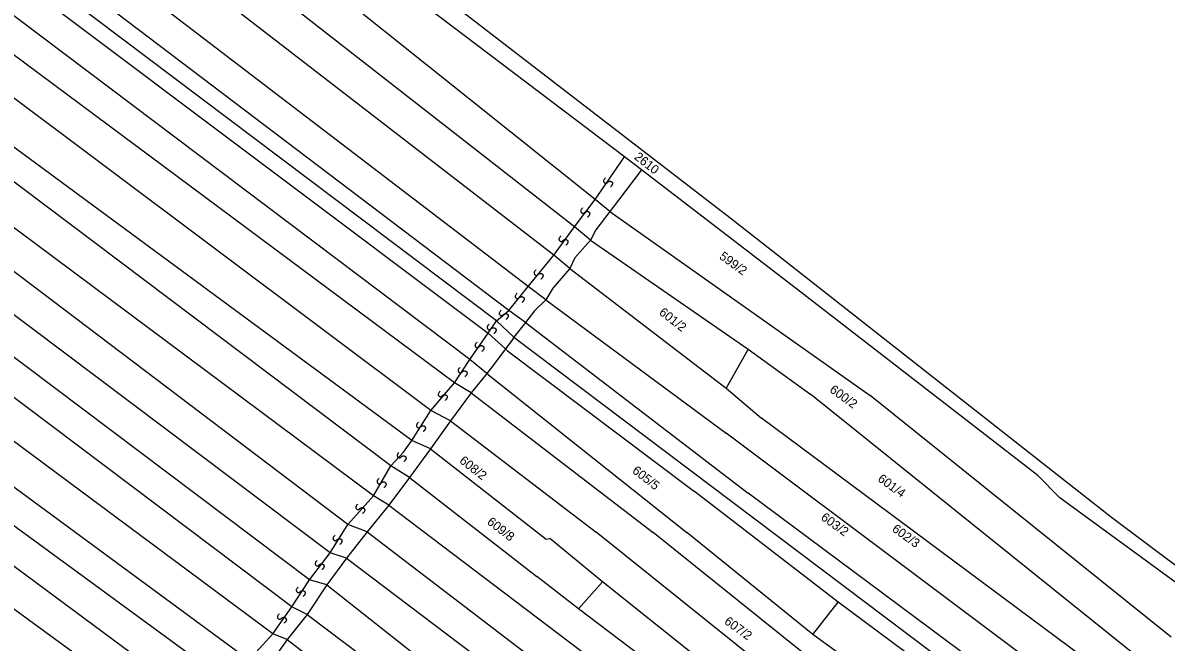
# Model space of a CAD drawing. Extents: x -581999 to -572728, y -1219553 to -1212032.
# Drawn here: x -577300.4 to -577046.4, y -1214683.3 to -1214545.7 of the extents above; entities that cross this region are included whole.
import ezdxf

# ---------------------------------------------------------------- set-up
doc = ezdxf.new("R2010")
doc.units = 0
for name, color, linetype in [('Vrstva 1', 7, 'Continuous'), ('Vrstva 2', 7, 'Continuous'), ('Vrstva 4', 7, 'Continuous'), ('Vrstva 6', 7, 'Continuous')]:
    doc.layers.add(name, color=color, linetype=linetype)

msp = doc.modelspace()

# ---------------------------------------------------------------- linework, layer by layer
at = {"layer": 'Vrstva 1'}
for p, q in [((-577173.2, -1214584.99), (-577388.875, -1214412.664)), ((-577177.814, -1214590.998), (-577393.467, -1214422.653)), ((-577182.425, -1214597.319), (-577397.014, -1214431.636)), ((-577188.1, -1214604.306), (-577399.497, -1214442.615)), ((-577192.44, -1214609.601), (-577401.268, -1214451.245)), ((-577195.178, -1214611.902), (-577402.391, -1214455.725)), ((-577403.465, -1214459.556), (-577196.983, -1214614.687)), ((-577201.069, -1214620.511), (-577405.865, -1214466.181)), ((-577204.509, -1214625.687), (-577407.639, -1214474.498)), ((-577209.72, -1214631.864), (-577409.72, -1214482.041)), ((-577213.976, -1214638.518), (-577414.023, -1214491.133)), ((-577218.587, -1214644.174), (-577416.861, -1214494.793)), ((-577222.489, -1214650.828), (-577423.245, -1214501.114)), ((-577228.164, -1214657.149), (-577427.856, -1214506.104)), ((-577232.066, -1214663.47), (-577433.26, -1214512.135)), ((-577236.677, -1214669.459), (-577438.393, -1214517.882)), ((-577240.578, -1214675.447), (-577443.108, -1214523.072)), ((-577244.835, -1214681.436), (-577449.136, -1214530.094)), ((-577250.174, -1214687.3), (-577454.627, -1214537.038)), ((-577253.702, -1214693.08), (-577459.151, -1214542.716)), ((-577258.313, -1214699.069), (-577462.971, -1214547.742)), ((-577262.569, -1214705.057), (-577467.937, -1214555.011)), ((-577162.904, -1214578.354), (-577166.7, -1214575.508)), ((-577170.008, -1214587.651), (-577173.2, -1214584.99)), ((-577174.264, -1214593.972), (-577177.814, -1214590.998)), ((-577178.875, -1214600.294), (-577182.425, -1214597.319)), ((-577184.195, -1214607.28), (-577188.1, -1214604.306)), ((-577188.711, -1214612.273), (-577192.44, -1214609.601)), ((-577191.284, -1214615.55), (-577195.178, -1214611.902)), ((-577193.144, -1214618.161), (-577196.983, -1214614.687)), ((-577191.713, -1214616.296), (-577193.144, -1214618.161)), ((-577191.284, -1214615.55), (-577065.274, -1214710.541)), ((-577193.144, -1214618.161), (-577195.94, -1214621.94)), ((-577192.695, -1214618.556), (-577193.144, -1214618.161)), ((-577197.32, -1214623.628), (-577201.069, -1214620.511)), ((-577200.79, -1214627.895), (-577204.509, -1214625.687)), ((-577205.332, -1214634.167), (-577209.72, -1214631.864)), ((-577209.808, -1214640.335), (-577213.976, -1214638.518)), ((-577214.507, -1214646.763), (-577218.587, -1214644.174)), ((-577219.047, -1214652.877), (-577222.489, -1214650.828)), ((-577223.897, -1214658.832), (-577228.164, -1214657.149)), ((-577228.435, -1214664.63), (-577232.066, -1214663.47)), ((-577232.819, -1214670.588), (-577236.677, -1214669.459)), ((-577237.207, -1214677.176), (-577240.578, -1214675.447)), ((-577241.673, -1214682.738), (-577244.835, -1214681.436))]:
    msp.add_line(p, q, dxfattribs=at)
for points in [[(-577166.7, -1214575.508), (-577251.364, -1214511.356), (-577280.716, -1214488.105)], [(-577143.306, -1214589.054), (-577228.604, -1214523.24), (-577244.701, -1214511.924)], [(-577039.499, -1214673.547), (-577070.025, -1214651.227), (-577074.89, -1214646.289), (-577128.538, -1214604.786), (-577162.904, -1214578.354), (-577168.07, -1214585.096)], [(-577168.07, -1214585.096), (-577170.008, -1214587.651), (-577173.08, -1214591.681)], [(-577170.008, -1214587.651), (-577112.132, -1214628.524)], [(-576930.254, -1214757.061), (-576935.99, -1214747.903), (-576959.905, -1214728.809), (-576982.36, -1214712.757), (-577058.553, -1214655.612), (-577135.842, -1214594.867), (-577143.306, -1214589.054)], [(-577173.08, -1214591.681), (-577174.264, -1214593.972), (-577177.778, -1214597.952)], [(-577174.264, -1214593.972), (-577139.259, -1214618.21)], [(-577177.778, -1214597.952), (-577178.875, -1214600.294), (-577182.634, -1214604.697)], [(-577178.875, -1214600.294), (-577144.115, -1214626.909)], [(-577182.634, -1214604.697), (-577184.195, -1214607.28), (-577186.702, -1214609.711)], [(-577186.702, -1214609.711), (-577188.711, -1214612.273), (-577191.284, -1214615.55), (-577191.713, -1214616.296)], [(-577184.195, -1214607.28), (-577144.115, -1214636.89)], [(-577188.711, -1214612.273), (-577139.236, -1214650.19)], [(-577192.695, -1214618.556), (-577151.196, -1214649.83)], [(-577139.259, -1214618.21), (-577144.115, -1214626.909)], [(-577139.259, -1214618.21), (-577125.314, -1214628.254)], [(-577195.94, -1214621.94), (-577197.32, -1214623.628), (-577200.79, -1214627.895)], [(-577197.32, -1214623.628), (-577152.883, -1214658.973)], [(-577144.115, -1214626.909), (-577136.312, -1214633.563)], [(-577200.79, -1214627.895), (-577205.332, -1214634.167)], [(-577200.79, -1214627.895), (-577160.362, -1214658.983)], [(-577049.661, -1214689.077), (-577125.314, -1214628.254)], [(-577045.273, -1214682.181), (-577112.132, -1214628.524)], [(-577205.332, -1214634.167), (-577209.808, -1214640.335)], [(-577205.332, -1214634.167), (-577173.006, -1214658.877)], [(-577053.701, -1214694.938), (-577136.312, -1214633.563)], [(-577058.086, -1214701.362), (-577144.115, -1214636.89)], [(-577209.808, -1214640.335), (-577214.507, -1214646.763)], [(-577209.808, -1214640.335), (-577184.096, -1214660.411), (-577183.332, -1214660.313)], [(-577214.507, -1214646.763), (-577219.047, -1214652.877)], [(-577214.507, -1214646.763), (-577186.205, -1214668.725)], [(-577119.273, -1214674.449), (-577151.196, -1214649.83)], [(-577062.16, -1214707.631), (-577139.236, -1214650.19)], [(-577219.047, -1214652.877), (-577223.897, -1214658.832)], [(-577219.047, -1214652.877), (-577164.908, -1214693.88)], [(-577223.897, -1214658.832), (-577228.435, -1214664.63)], [(-577223.897, -1214658.832), (-577179.208, -1214692.919)], [(-577171.581, -1214669.881), (-577183.332, -1214660.313)], [(-577079.7, -1214733.798), (-577173.006, -1214658.877)], [(-577075.315, -1214727.217), (-577160.362, -1214658.983)], [(-577124.863, -1214681.597), (-577152.883, -1214658.973)], [(-577228.435, -1214664.63), (-577232.819, -1214670.588)], [(-577228.435, -1214664.63), (-577189.2, -1214694.359)], [(-577232.819, -1214670.588), (-577237.207, -1214677.176)], [(-577232.819, -1214670.588), (-577191.421, -1214703.301)], [(-577176.933, -1214675.904), (-577186.205, -1214668.725)], [(-577176.933, -1214675.904), (-577171.581, -1214669.881)], [(-577083.62, -1214740.224), (-577171.581, -1214669.881)], [(-577124.863, -1214681.597), (-577119.273, -1214674.449)], [(-577066.387, -1214713.741), (-577119.273, -1214674.449)], [(-577237.207, -1214677.176), (-577241.673, -1214682.738)], [(-577237.207, -1214677.176), (-577190.483, -1214712.437)], [(-577104.63, -1214730.744), (-577176.933, -1214675.904)], [(-577241.673, -1214682.738), (-577246.058, -1214689.011)], [(-577241.673, -1214682.738), (-577193.003, -1214720.312)], [(-577070.932, -1214720.95), (-577124.863, -1214681.597)]]:
    msp.add_lwpolyline(points, dxfattribs=at)
at = {"layer": 'Vrstva 4'}
for p, q in [((-577192.44, -1214609.601), (-577188.1, -1214604.306)), ((-577195.178, -1214611.902), (-577192.44, -1214609.601)), ((-577196.983, -1214614.687), (-577195.178, -1214611.902)), ((-577201.069, -1214620.511), (-577196.983, -1214614.687)), ((-577204.509, -1214625.687), (-577201.069, -1214620.511)), ((-577209.72, -1214631.864), (-577204.509, -1214625.687)), ((-577213.976, -1214638.518), (-577209.72, -1214631.864)), ((-577215.808, -1214641.119), (-577213.976, -1214638.518)), ((-577228.164, -1214657.149), (-577222.489, -1214650.828)), ((-577232.066, -1214663.47), (-577228.164, -1214657.149)), ((-577236.677, -1214669.459), (-577232.066, -1214663.47)), ((-577240.578, -1214675.447), (-577236.677, -1214669.459)), ((-577244.835, -1214681.436), (-577240.578, -1214675.447)), ((-577250.174, -1214687.3), (-577244.835, -1214681.436))]:
    msp.add_line(p, q, dxfattribs=at)
for points in [[(-577188.1, -1214604.306), (-577182.425, -1214597.319), (-577177.814, -1214590.998), (-577173.2, -1214584.99), (-577166.7, -1214575.508)], [(-577222.489, -1214650.828), (-577218.587, -1214644.174), (-577215.808, -1214641.119)]]:
    msp.add_lwpolyline(points, dxfattribs=at)
at = {"layer": 'Vrstva 6'}
for points in [[(-577170.962, -1214580.13), (-577171.549, -1214580.752), (-577171.094, -1214581.361), (-577170.688, -1214581.349), (-577170.402, -1214581.044), (-577170.096, -1214580.89), (-577169.796, -1214580.906), (-577169.589, -1214581.008), (-577169.413, -1214581.211), (-577169.368, -1214581.575), (-577169.703, -1214582.087), (-577169.861, -1214582.179)], [(-577176.016, -1214586.817), (-577176.603, -1214587.439), (-577176.148, -1214588.048), (-577175.742, -1214588.036), (-577175.456, -1214587.731), (-577175.15, -1214587.577), (-577174.85, -1214587.593), (-577174.643, -1214587.695), (-577174.467, -1214587.898), (-577174.422, -1214588.262), (-577174.757, -1214588.774), (-577174.915, -1214588.866)], [(-577180.854, -1214593.072), (-577181.441, -1214593.694), (-577180.986, -1214594.303), (-577180.58, -1214594.291), (-577180.294, -1214593.986), (-577179.988, -1214593.832), (-577179.688, -1214593.848), (-577179.481, -1214593.95), (-577179.305, -1214594.153), (-577179.26, -1214594.517), (-577179.595, -1214595.029), (-577179.753, -1214595.121)], [(-577186.385, -1214600.597), (-577186.972, -1214601.219), (-577186.517, -1214601.828), (-577186.111, -1214601.816), (-577185.825, -1214601.511), (-577185.519, -1214601.357), (-577185.219, -1214601.373), (-577185.012, -1214601.475), (-577184.836, -1214601.678), (-577184.791, -1214602.042), (-577185.126, -1214602.554), (-577185.284, -1214602.646)], [(-577190.579, -1214605.774), (-577191.166, -1214606.396), (-577190.711, -1214607.005), (-577190.305, -1214606.993), (-577190.019, -1214606.688), (-577189.713, -1214606.534), (-577189.413, -1214606.55), (-577189.206, -1214606.652), (-577189.03, -1214606.855), (-577188.985, -1214607.219), (-577189.32, -1214607.731), (-577189.478, -1214607.823)], [(-577194.127, -1214609.548), (-577194.714, -1214610.17), (-577194.259, -1214610.779), (-577193.853, -1214610.767), (-577193.567, -1214610.462), (-577193.261, -1214610.308), (-577192.961, -1214610.324), (-577192.754, -1214610.426), (-577192.578, -1214610.629), (-577192.533, -1214610.993), (-577192.868, -1214611.505), (-577193.026, -1214611.597)], [(-577196.815, -1214612.676), (-577197.402, -1214613.298), (-577196.947, -1214613.907), (-577196.541, -1214613.895), (-577196.255, -1214613.59), (-577195.949, -1214613.436), (-577195.649, -1214613.452), (-577195.442, -1214613.554), (-577195.266, -1214613.757), (-577195.221, -1214614.121), (-577195.556, -1214614.633), (-577195.714, -1214614.725)], [(-577199.503, -1214616.666), (-577200.09, -1214617.288), (-577199.635, -1214617.897), (-577199.229, -1214617.885), (-577198.943, -1214617.58), (-577198.637, -1214617.426), (-577198.337, -1214617.442), (-577198.13, -1214617.544), (-577197.954, -1214617.747), (-577197.909, -1214618.111), (-577198.244, -1214618.623), (-577198.402, -1214618.715)], [(-577203.266, -1214622.274), (-577203.853, -1214622.896), (-577203.398, -1214623.505), (-577202.992, -1214623.493), (-577202.706, -1214623.188), (-577202.4, -1214623.034), (-577202.1, -1214623.05), (-577201.893, -1214623.152), (-577201.717, -1214623.355), (-577201.672, -1214623.719), (-577202.007, -1214624.231), (-577202.165, -1214624.323)], [(-577207.675, -1214627.559), (-577208.262, -1214628.181), (-577207.807, -1214628.79), (-577207.401, -1214628.778), (-577207.115, -1214628.473), (-577206.809, -1214628.319), (-577206.509, -1214628.335), (-577206.302, -1214628.437), (-577206.126, -1214628.64), (-577206.081, -1214629.004), (-577206.416, -1214629.516), (-577206.574, -1214629.608)], [(-577212.513, -1214634.461), (-577213.1, -1214635.083), (-577212.645, -1214635.692), (-577212.239, -1214635.68), (-577211.953, -1214635.375), (-577211.647, -1214635.221), (-577211.347, -1214635.237), (-577211.14, -1214635.339), (-577210.964, -1214635.542), (-577210.919, -1214635.906), (-577211.254, -1214636.418), (-577211.412, -1214636.51)], [(-577216.814, -1214641.147), (-577217.401, -1214641.769), (-577216.946, -1214642.378), (-577216.54, -1214642.366), (-577216.254, -1214642.061), (-577215.948, -1214641.907), (-577215.648, -1214641.923), (-577215.441, -1214642.025), (-577215.265, -1214642.228), (-577215.22, -1214642.592), (-577215.555, -1214643.104), (-577215.713, -1214643.196)], [(-577221.258, -1214646.936), (-577221.845, -1214647.558), (-577221.39, -1214648.167), (-577220.984, -1214648.155), (-577220.698, -1214647.85), (-577220.392, -1214647.696), (-577220.092, -1214647.712), (-577219.885, -1214647.814), (-577219.709, -1214648.017), (-577219.664, -1214648.381), (-577219.999, -1214648.893), (-577220.157, -1214648.985)], [(-577225.989, -1214652.652), (-577226.576, -1214653.274), (-577226.121, -1214653.883), (-577225.715, -1214653.871), (-577225.429, -1214653.566), (-577225.123, -1214653.412), (-577224.823, -1214653.428), (-577224.616, -1214653.53), (-577224.44, -1214653.733), (-577224.395, -1214654.097), (-577224.73, -1214654.609), (-577224.888, -1214654.701)], [(-577231.042, -1214659.554), (-577231.629, -1214660.176), (-577231.174, -1214660.785), (-577230.768, -1214660.773), (-577230.482, -1214660.468), (-577230.176, -1214660.314), (-577229.876, -1214660.33), (-577229.669, -1214660.432), (-577229.493, -1214660.635), (-577229.448, -1214660.999), (-577229.783, -1214661.511), (-577229.941, -1214661.603)], [(-577235.021, -1214665.162), (-577235.608, -1214665.784), (-577235.153, -1214666.393), (-577234.747, -1214666.381), (-577234.461, -1214666.076), (-577234.155, -1214665.922), (-577233.855, -1214665.938), (-577233.648, -1214666.04), (-577233.472, -1214666.243), (-577233.427, -1214666.607), (-577233.762, -1214667.119), (-577233.92, -1214667.211)], [(-577239.214, -1214671.094), (-577239.801, -1214671.716), (-577239.346, -1214672.325), (-577238.94, -1214672.313), (-577238.654, -1214672.008), (-577238.348, -1214671.854), (-577238.048, -1214671.87), (-577237.841, -1214671.972), (-577237.665, -1214672.175), (-577237.62, -1214672.539), (-577237.955, -1214673.051), (-577238.113, -1214673.143)], [(-577243.407, -1214677.026), (-577243.994, -1214677.648), (-577243.539, -1214678.257), (-577243.133, -1214678.245), (-577242.847, -1214677.94), (-577242.541, -1214677.786), (-577242.241, -1214677.802), (-577242.034, -1214677.904), (-577241.858, -1214678.107), (-577241.813, -1214678.471), (-577242.148, -1214678.983), (-577242.306, -1214679.075)]]:
    msp.add_open_spline(points, degree=2, dxfattribs=at)

# ---------------------------------------------------------------- texts
at = {"layer": 'Vrstva 2'}
for s, rotation, p in [('2610', 321.94113, (-577164.716, -1214575.818)), ('599/2', 324.13776, (-577145.832, -1214597.974)), ('601/2', 321.94113, (-577159.203, -1214610.352)), ('600/2', 324.13776, (-577121.317, -1214627.594)), ('608/2', 321.94113, (-577203.554, -1214643.312)), ('605/5', 321.94113, (-577165.164, -1214645.532)), ('601/4', 324.13776, (-577110.627, -1214647.404)), ('603/2', 324.13776, (-577123.26, -1214655.981)), ('609/8', 321.94113, (-577197.409, -1214656.907)), ('602/3', 324.13776, (-577107.45, -1214658.538)), ('607/2', 324.13776, (-577144.717, -1214679.081))]:
    msp.add_text(s, height=2, rotation=rotation, dxfattribs=at).set_placement(p)

doc.saveas('drawing.dxf')
